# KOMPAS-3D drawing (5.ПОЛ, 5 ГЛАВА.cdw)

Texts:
  ДП.11.213.05.000.00.ЭМ
  Телятник на 120 голов в СПК колхоз "Дзержинского" Даниловского МР Ярославской обл.
  УСЛОВНЫЕ ОБОЗНАЧЕНИЯ
  - пульт распределительнай марки ПР85-067
  № поз.
  Наименование помещения
  Площадь,
  Стойловое
  Веткабинет
  Инвентарная
  Венткамера
  Электрощитовая
  Служебная
  Санузел
  Кладовая дезосредств
  Фуражная
  Помещение для приготовления ЗЦМ
  Помещение для погрузки навоза в ТС
  Коридор
  ЭКСПЛИКАЦИЯ ПОМЕЩЕНИЙ
  ввод в здание
  ПР85-067
  ВВГ (4 х 2,5)
  ВВГ (4 х 25)
  ШУ-1
  ТРБ - 10
  шинный канал
  ПВ4(1х2,5)
  - шкаф управления системой обогрева пола
  - провод нагревательный марки ПОСХВ
  - линия силовой электропроводки
  - датчик температуры
  - тиристорный регулируемый блок ТРБ-10
  Куракин
  ФГОУ ВПО ЯГСХА
  Телятник на 120 голов
  в СПК колхоз "Дзержинского"
  Даниловского МР Ярославской обл.
  Шмигель
  Система обогрева пола.
  ДП08Ф040200009Э0-
  Королёва
  Орлов
Dimensions and other numbers on the sheet: 1; 2; 3; 4; 5; 6; 7; 8; 9; 10; 11; 12; 504; 16,6; 15,7; 29,5; 11,0; 25,0; 3,8; 12,2; 14,7; 27,5; 22,4; 30,1; 12000; 42000; 30000; 6000; 4500; 3500х150х150 мм; 28; 14; 1:100; 0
